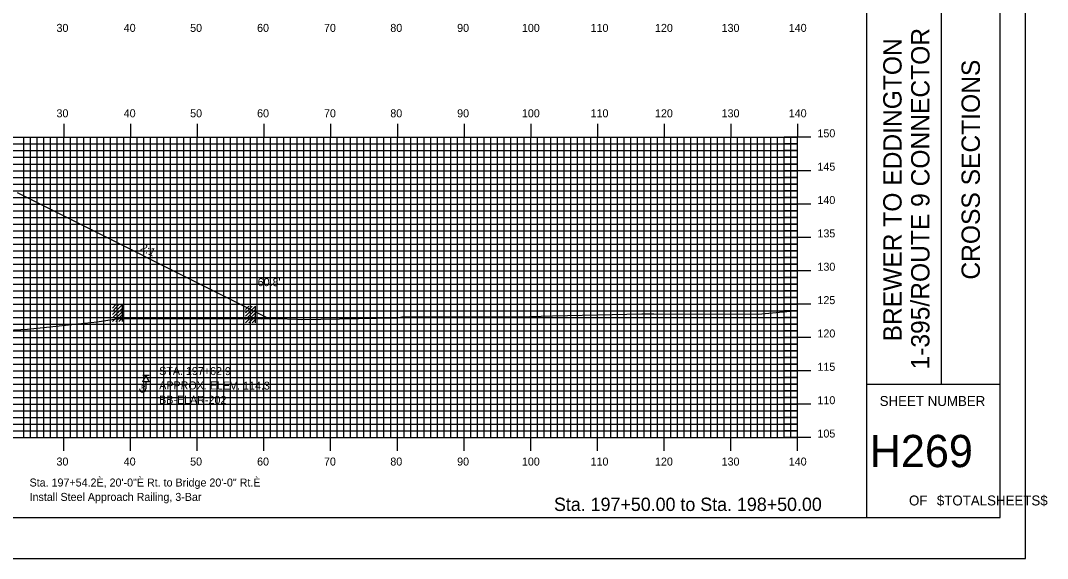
# Model space of a CAD drawing. Extents: x 1790124 to 1790467, y 442591 to 442811.
# Drawn here: x 1790313.2 to 1790467.2, y 442590.5 to 442671.2 of the extents above; entities that cross this region are included whole.
import ezdxf

# ---------------------------------------------------------------- set-up
doc = ezdxf.new("R2010")
doc.units = 0
for name, color, linetype in [('ANNOTATION', 7, 'Continuous'), ('BORDER', 7, 'Continuous'), ('BORING - REFUSAL', 7, 'Continuous'), ('D_Text_Standard', 7, 'Continuous'), ('H_V ANNOTATION', 7, 'Continuous'), ('M_Buildings_Rooftop', 7, 'Continuous'), ('M_Utilities_Pole', 7, 'Continuous'), ('MAJOR', 7, 'Continuous'), ('MINOR', 7, 'Continuous'), ('PLOT BOUNDARY', 7, 'Continuous'), ('S_Roadway_Centerline', 7, 'Continuous')]:
    doc.layers.add(name, color=color, linetype=linetype)

msp = doc.modelspace()

# ---------------------------------------------------------------- linework, layer by layer
at = {"layer": 'ANNOTATION'}
msp.add_line((1790312.7, 442645.4), (1790350.54, 442626.48), dxfattribs=at)
at = {"layer": 'BORDER'}
for p, q in [((1790440.1, 442596.67), (1790440.1, 442806.67)), ((1790451.28, 442616.67), (1790451.28, 442686.67)), ((1790440.1, 442616.67), (1790460.1, 442616.67))]:
    msp.add_line(p, q, dxfattribs=at)
msp.add_lwpolyline([(1790140.1, 442596.67), (1790460.1, 442596.67), (1790460.1, 442806.67), (1790140.1, 442806.67)], close=True, dxfattribs=at)
at = {"layer": 'BORING - REFUSAL'}
for p, q in [((1790332.48, 442617.97), (1790331.52, 442617.97)), ((1790332, 442617.01), (1790332, 442615.95))]:
    msp.add_line(p, q, dxfattribs=at)
msp.add_lwpolyline([(1790332, 442617.97), (1790332.48, 442617.01), (1790331.52, 442617.01)], close=True, dxfattribs=at)
msp.add_arc((1790331.51, 442615.95), 0.485, 180, 0, dxfattribs=at)
at = {"layer": 'M_Buildings_Rooftop'}
for p, q in [((1790326.98, 442627.09), (1790328.49, 442628.6)), ((1790326.98, 442627.58), (1790327.96, 442628.6)), ((1790326.98, 442628.08), (1790327.47, 442628.6)), ((1790326.98, 442626.6), (1790328.49, 442628.08)), ((1790328.49, 442626.07), (1790328.49, 442628.6)), ((1790346.95, 442626.87), (1790348.45, 442628.38)), ((1790346.95, 442627.36), (1790347.93, 442628.38)), ((1790346.95, 442627.85), (1790347.44, 442628.38)), ((1790346.95, 442626.38), (1790348.45, 442627.85)), ((1790348.45, 442625.85), (1790348.45, 442628.38)), ((1790326.98, 442626.07), (1790328.49, 442627.58)), ((1790327.47, 442626.07), (1790328.49, 442627.09)), ((1790327.96, 442626.07), (1790328.49, 442626.6)), ((1790346.95, 442625.85), (1790348.45, 442627.36)), ((1790347.44, 442625.85), (1790348.45, 442626.87)), ((1790347.93, 442625.85), (1790348.45, 442626.38))]:
    msp.add_line(p, q, dxfattribs=at)
at = {"layer": 'M_Utilities_Pole'}
msp.add_line((1790317.84, 442626.06), (1790317.84, 442626.04), dxfattribs=at)
msp.add_circle((1790317.84, 442626.05), 0.00417, dxfattribs=at)
at = {"layer": 'MAJOR'}
for p, q in [((1790319.7, 442655.67), (1790319.7, 442653.67)), ((1790329.7, 442655.67), (1790329.7, 442653.67)), ((1790339.7, 442655.67), (1790339.7, 442653.67)), ((1790349.7, 442655.67), (1790349.7, 442653.67)), ((1790359.7, 442655.67), (1790359.7, 442653.67)), ((1790369.7, 442655.67), (1790369.7, 442653.67)), ((1790379.7, 442655.67), (1790379.7, 442653.67)), ((1790389.7, 442655.67), (1790389.7, 442653.67)), ((1790399.7, 442655.67), (1790399.7, 442653.67)), ((1790409.7, 442655.67), (1790409.7, 442653.67)), ((1790419.7, 442655.67), (1790419.7, 442653.67)), ((1790429.7, 442655.67), (1790429.7, 442653.67)), ((1790149.7, 442653.67), (1790429.7, 442653.67)), ((1790149.7, 442653.67), (1790429.7, 442653.67)), ((1790319.7, 442608.67), (1790319.7, 442653.67)), ((1790329.7, 442608.67), (1790329.7, 442653.67)), ((1790339.7, 442608.67), (1790339.7, 442653.67)), ((1790349.7, 442608.67), (1790349.7, 442653.67)), ((1790359.7, 442608.67), (1790359.7, 442653.67)), ((1790369.7, 442608.67), (1790369.7, 442653.67)), ((1790379.7, 442608.67), (1790379.7, 442653.67)), ((1790389.7, 442608.67), (1790389.7, 442653.67)), ((1790399.7, 442608.67), (1790399.7, 442653.67)), ((1790409.7, 442608.67), (1790409.7, 442653.67)), ((1790419.7, 442608.67), (1790419.7, 442653.67)), ((1790431.7, 442653.67), (1790427.69, 442653.67)), ((1790429.7, 442608.67), (1790429.7, 442653.67)), ((1790429.7, 442608.67), (1790429.7, 442653.67)), ((1790149.7, 442648.67), (1790429.7, 442648.67)), ((1790431.7, 442648.67), (1790427.69, 442648.67)), ((1790149.7, 442643.67), (1790429.7, 442643.67)), ((1790431.7, 442643.67), (1790427.69, 442643.67)), ((1790149.7, 442638.67), (1790429.7, 442638.67)), ((1790431.7, 442638.67), (1790427.69, 442638.67)), ((1790149.7, 442633.67), (1790429.7, 442633.67)), ((1790431.7, 442633.67), (1790427.69, 442633.67)), ((1790149.7, 442628.67), (1790429.7, 442628.67)), ((1790431.7, 442628.67), (1790427.69, 442628.67)), ((1790149.7, 442623.67), (1790429.7, 442623.67)), ((1790431.7, 442623.67), (1790427.69, 442623.67)), ((1790149.7, 442618.67), (1790429.7, 442618.67)), ((1790431.7, 442618.67), (1790427.69, 442618.67)), ((1790149.7, 442613.67), (1790429.7, 442613.67)), ((1790431.7, 442613.67), (1790427.69, 442613.67)), ((1790149.7, 442608.67), (1790429.7, 442608.67)), ((1790149.7, 442608.67), (1790429.7, 442608.67)), ((1790319.7, 442606.66), (1790319.7, 442608.67)), ((1790329.7, 442606.66), (1790329.7, 442608.67)), ((1790339.7, 442606.66), (1790339.7, 442608.67)), ((1790349.7, 442606.66), (1790349.7, 442608.67)), ((1790359.7, 442606.66), (1790359.7, 442608.67)), ((1790369.7, 442606.66), (1790369.7, 442608.67)), ((1790379.7, 442606.66), (1790379.7, 442608.67)), ((1790389.7, 442606.66), (1790389.7, 442608.67)), ((1790399.7, 442606.66), (1790399.7, 442608.67)), ((1790409.7, 442606.66), (1790409.7, 442608.67)), ((1790419.7, 442606.66), (1790419.7, 442608.67)), ((1790431.7, 442608.67), (1790427.69, 442608.67)), ((1790429.7, 442606.66), (1790429.7, 442608.67))]:
    msp.add_line(p, q, dxfattribs=at)
at = {"layer": 'MINOR'}
for p, q in [((1790149.7, 442652.67), (1790429.7, 442652.67)), ((1790313.7, 442608.67), (1790313.7, 442653.67)), ((1790314.7, 442608.67), (1790314.7, 442653.67)), ((1790315.7, 442608.67), (1790315.7, 442653.67)), ((1790316.7, 442608.67), (1790316.7, 442653.67)), ((1790317.7, 442608.67), (1790317.7, 442653.67)), ((1790318.7, 442608.67), (1790318.7, 442653.67)), ((1790320.7, 442608.67), (1790320.7, 442653.67)), ((1790321.7, 442608.67), (1790321.7, 442653.67)), ((1790322.7, 442608.67), (1790322.7, 442653.67)), ((1790323.7, 442608.67), (1790323.7, 442653.67)), ((1790324.7, 442608.67), (1790324.7, 442653.67)), ((1790325.7, 442608.67), (1790325.7, 442653.67)), ((1790326.7, 442608.67), (1790326.7, 442653.67)), ((1790327.7, 442608.67), (1790327.7, 442653.67)), ((1790328.7, 442608.67), (1790328.7, 442653.67)), ((1790330.7, 442608.67), (1790330.7, 442653.67)), ((1790331.7, 442608.67), (1790331.7, 442653.67)), ((1790332.7, 442608.67), (1790332.7, 442653.67)), ((1790333.7, 442608.67), (1790333.7, 442653.67)), ((1790334.7, 442608.67), (1790334.7, 442653.67)), ((1790335.7, 442608.67), (1790335.7, 442653.67)), ((1790336.7, 442608.67), (1790336.7, 442653.67)), ((1790337.7, 442608.67), (1790337.7, 442653.67)), ((1790338.7, 442608.67), (1790338.7, 442653.67)), ((1790340.7, 442608.67), (1790340.7, 442653.67)), ((1790341.7, 442608.67), (1790341.7, 442653.67)), ((1790342.7, 442608.67), (1790342.7, 442653.67)), ((1790343.7, 442608.67), (1790343.7, 442653.67)), ((1790344.7, 442608.67), (1790344.7, 442653.67)), ((1790345.7, 442608.67), (1790345.7, 442653.67)), ((1790346.7, 442608.67), (1790346.7, 442653.67)), ((1790347.7, 442608.67), (1790347.7, 442653.67)), ((1790348.7, 442608.67), (1790348.7, 442653.67)), ((1790350.7, 442608.67), (1790350.7, 442653.67)), ((1790351.7, 442608.67), (1790351.7, 442653.67)), ((1790352.7, 442608.67), (1790352.7, 442653.67)), ((1790353.7, 442608.67), (1790353.7, 442653.67)), ((1790354.7, 442608.67), (1790354.7, 442653.67)), ((1790355.7, 442608.67), (1790355.7, 442653.67)), ((1790356.7, 442608.67), (1790356.7, 442653.67)), ((1790357.7, 442608.67), (1790357.7, 442653.67)), ((1790358.7, 442608.67), (1790358.7, 442653.67)), ((1790360.7, 442608.67), (1790360.7, 442653.67)), ((1790361.7, 442608.67), (1790361.7, 442653.67)), ((1790362.7, 442608.67), (1790362.7, 442653.67)), ((1790363.7, 442608.67), (1790363.7, 442653.67)), ((1790364.7, 442608.67), (1790364.7, 442653.67)), ((1790365.7, 442608.67), (1790365.7, 442653.67)), ((1790366.7, 442608.67), (1790366.7, 442653.67)), ((1790367.7, 442608.67), (1790367.7, 442653.67)), ((1790368.7, 442608.67), (1790368.7, 442653.67)), ((1790370.7, 442608.67), (1790370.7, 442653.67)), ((1790371.7, 442608.67), (1790371.7, 442653.67)), ((1790372.7, 442608.67), (1790372.7, 442653.67)), ((1790373.7, 442608.67), (1790373.7, 442653.67)), ((1790374.7, 442608.67), (1790374.7, 442653.67)), ((1790375.7, 442608.67), (1790375.7, 442653.67)), ((1790376.7, 442608.67), (1790376.7, 442653.67)), ((1790377.7, 442608.67), (1790377.7, 442653.67)), ((1790378.7, 442608.67), (1790378.7, 442653.67)), ((1790380.7, 442608.67), (1790380.7, 442653.67)), ((1790381.7, 442608.67), (1790381.7, 442653.67)), ((1790382.7, 442608.67), (1790382.7, 442653.67)), ((1790383.7, 442608.67), (1790383.7, 442653.67)), ((1790384.7, 442608.67), (1790384.7, 442653.67)), ((1790385.7, 442608.67), (1790385.7, 442653.67)), ((1790386.7, 442608.67), (1790386.7, 442653.67)), ((1790387.7, 442608.67), (1790387.7, 442653.67)), ((1790388.7, 442608.67), (1790388.7, 442653.67)), ((1790390.7, 442608.67), (1790390.7, 442653.67)), ((1790391.7, 442608.67), (1790391.7, 442653.67)), ((1790392.7, 442608.67), (1790392.7, 442653.67)), ((1790393.7, 442608.67), (1790393.7, 442653.67)), ((1790394.7, 442608.67), (1790394.7, 442653.67)), ((1790395.7, 442608.67), (1790395.7, 442653.67)), ((1790396.7, 442608.67), (1790396.7, 442653.67)), ((1790397.7, 442608.67), (1790397.7, 442653.67)), ((1790398.7, 442608.67), (1790398.7, 442653.67)), ((1790400.7, 442608.67), (1790400.7, 442653.67)), ((1790401.7, 442608.67), (1790401.7, 442653.67)), ((1790402.7, 442608.67), (1790402.7, 442653.67)), ((1790403.7, 442608.67), (1790403.7, 442653.67)), ((1790404.7, 442608.67), (1790404.7, 442653.67)), ((1790405.7, 442608.67), (1790405.7, 442653.67)), ((1790406.7, 442608.67), (1790406.7, 442653.67)), ((1790407.7, 442608.67), (1790407.7, 442653.67)), ((1790408.7, 442608.67), (1790408.7, 442653.67)), ((1790410.7, 442608.67), (1790410.7, 442653.67)), ((1790411.7, 442608.67), (1790411.7, 442653.67)), ((1790412.7, 442608.67), (1790412.7, 442653.67)), ((1790413.7, 442608.67), (1790413.7, 442653.67)), ((1790414.7, 442608.67), (1790414.7, 442653.67)), ((1790415.7, 442608.67), (1790415.7, 442653.67)), ((1790416.7, 442608.67), (1790416.7, 442653.67)), ((1790417.7, 442608.67), (1790417.7, 442653.67)), ((1790418.7, 442608.67), (1790418.7, 442653.67)), ((1790420.7, 442608.67), (1790420.7, 442653.67)), ((1790421.7, 442608.67), (1790421.7, 442653.67)), ((1790422.7, 442608.67), (1790422.7, 442653.67)), ((1790423.7, 442608.67), (1790423.7, 442653.67)), ((1790424.7, 442608.67), (1790424.7, 442653.67)), ((1790425.7, 442608.67), (1790425.7, 442653.67)), ((1790426.7, 442608.67), (1790426.7, 442653.67)), ((1790429.7, 442652.67), (1790427.69, 442652.67)), ((1790427.7, 442608.67), (1790427.7, 442653.67)), ((1790428.7, 442608.67), (1790428.7, 442653.67)), ((1790149.7, 442651.67), (1790429.7, 442651.67)), ((1790429.7, 442651.67), (1790427.69, 442651.67)), ((1790149.7, 442650.67), (1790429.7, 442650.67)), ((1790149.7, 442649.67), (1790429.7, 442649.67)), ((1790429.7, 442650.67), (1790427.69, 442650.67)), ((1790429.7, 442649.67), (1790427.69, 442649.67)), ((1790149.7, 442647.67), (1790429.7, 442647.67)), ((1790149.7, 442646.67), (1790429.7, 442646.67)), ((1790429.7, 442647.67), (1790427.69, 442647.67)), ((1790429.7, 442646.67), (1790427.69, 442646.67)), ((1790149.7, 442645.67), (1790429.7, 442645.67)), ((1790429.7, 442645.67), (1790427.69, 442645.67)), ((1790149.7, 442644.67), (1790429.7, 442644.67)), ((1790429.7, 442644.67), (1790427.69, 442644.67)), ((1790149.7, 442642.67), (1790429.7, 442642.67)), ((1790429.7, 442642.67), (1790427.69, 442642.67)), ((1790149.7, 442641.67), (1790429.7, 442641.67)), ((1790149.7, 442640.67), (1790429.7, 442640.67)), ((1790429.7, 442641.67), (1790427.69, 442641.67)), ((1790429.7, 442640.67), (1790427.69, 442640.67)), ((1790149.7, 442639.67), (1790429.7, 442639.67)), ((1790429.7, 442639.67), (1790427.69, 442639.67)), ((1790149.7, 442637.67), (1790429.7, 442637.67)), ((1790429.7, 442637.67), (1790427.69, 442637.67)), ((1790149.7, 442636.67), (1790429.7, 442636.67)), ((1790149.7, 442635.67), (1790429.7, 442635.67)), ((1790429.7, 442636.67), (1790427.69, 442636.67)), ((1790429.7, 442635.67), (1790427.69, 442635.67)), ((1790149.7, 442634.67), (1790429.7, 442634.67)), ((1790429.7, 442634.67), (1790427.69, 442634.67)), ((1790149.7, 442632.67), (1790429.7, 442632.67)), ((1790429.7, 442632.67), (1790427.69, 442632.67)), ((1790149.7, 442631.67), (1790429.7, 442631.67)), ((1790429.7, 442631.67), (1790427.69, 442631.67)), ((1790149.7, 442630.67), (1790429.7, 442630.67)), ((1790149.7, 442629.67), (1790429.7, 442629.67)), ((1790429.7, 442630.67), (1790427.69, 442630.67)), ((1790429.7, 442629.67), (1790427.69, 442629.67)), ((1790149.7, 442627.67), (1790429.7, 442627.67)), ((1790149.7, 442626.67), (1790429.7, 442626.67)), ((1790429.7, 442627.67), (1790427.69, 442627.67)), ((1790429.7, 442626.67), (1790427.69, 442626.67)), ((1790149.7, 442625.67), (1790429.7, 442625.67)), ((1790429.7, 442625.67), (1790427.69, 442625.67)), ((1790149.7, 442624.67), (1790429.7, 442624.67)), ((1790429.7, 442624.67), (1790427.69, 442624.67)), ((1790149.7, 442622.67), (1790429.7, 442622.67)), ((1790429.7, 442622.67), (1790427.69, 442622.67)), ((1790149.7, 442621.67), (1790429.7, 442621.67)), ((1790149.7, 442620.67), (1790429.7, 442620.67)), ((1790429.7, 442621.67), (1790427.69, 442621.67)), ((1790429.7, 442620.67), (1790427.69, 442620.67)), ((1790149.7, 442619.67), (1790429.7, 442619.67)), ((1790429.7, 442619.67), (1790427.69, 442619.67)), ((1790149.7, 442617.67), (1790429.7, 442617.67)), ((1790429.7, 442617.67), (1790427.69, 442617.67)), ((1790149.7, 442616.67), (1790429.7, 442616.67)), ((1790149.7, 442615.67), (1790429.7, 442615.67)), ((1790429.7, 442616.67), (1790427.69, 442616.67)), ((1790429.7, 442615.67), (1790427.69, 442615.67)), ((1790149.7, 442614.67), (1790429.7, 442614.67)), ((1790429.7, 442614.67), (1790427.69, 442614.67)), ((1790149.7, 442612.67), (1790429.7, 442612.67)), ((1790429.7, 442612.67), (1790427.69, 442612.67)), ((1790149.7, 442611.67), (1790429.7, 442611.67)), ((1790429.7, 442611.67), (1790427.69, 442611.67)), ((1790149.7, 442610.67), (1790429.7, 442610.67)), ((1790149.7, 442609.67), (1790429.7, 442609.67)), ((1790429.7, 442610.67), (1790427.69, 442610.67)), ((1790429.7, 442609.67), (1790427.69, 442609.67))]:
    msp.add_line(p, q, dxfattribs=at)
at = {"layer": 'PLOT BOUNDARY'}
msp.add_lwpolyline([(1790123.91, 442590.55), (1790463.91, 442590.55), (1790463.91, 442810.55), (1790123.91, 442810.55)], close=True, dxfattribs=at)
at = {"layer": 'S_Roadway_Centerline'}
msp.add_lwpolyline([(1790308.09, 442624.59), (1790314.26, 442624.9), (1790324.7, 442626.01), (1790326.28, 442626.25), (1790327.6, 442626.48), (1790331.09, 442626.51), (1790349.29, 442626.47), (1790351.76, 442626.49), (1790354.62, 442626.4), (1790355.39, 442626.35), (1790369.53, 442626.59), (1790369.73, 442626.6), (1790369.75, 442626.61), (1790370.39, 442626.74), (1790372.69, 442626.74), (1790376.59, 442626.75), (1790389.57, 442626.81), (1790392.97, 442626.93), (1790406.37, 442627.21), (1790406.95, 442627.23), (1790408.15, 442627.21), (1790423.83, 442627.18), (1790429.7, 442627.71)], dxfattribs=at)

# ---------------------------------------------------------------- texts
at = {"layer": 'ANNOTATION'}
msp.add_text('2:1', height=1.2, rotation=333.4349, dxfattribs=at).set_placement((1790331.05, 442636.76))
for s, p in [('Sta. 197+54.2È, 20\'-0"È Rt. to Bridge 20\'-0" Rt.È', (1790314.55, 442601.33)), ('Install Steel Approach Railing, 3-Bar', (1790314.55, 442599.17))]:
    msp.add_text(s, height=1.2, dxfattribs=at).set_placement(p)
at = {"layer": 'BORDER'}
for s, p in [('1-395/ROUTE 9 CONNECTOR', (1790449.5, 442618.87)), ('BREWER TO EDDINGTON', (1790445.32, 442623.07)), ('CROSS SECTIONS', (1790457.06, 442632.34))]:
    msp.add_text(s, height=2.7557, rotation=90, dxfattribs=at).set_placement(p)
for s, height, p in [('SHEET NUMBER', 1.4905, (1790442.03, 442613.4)), ('H269', 4.839, (1790440.54, 442604.23)), ('OF', 1.491, (1790446.43, 442598.49)), ('$TOTALSHEETS$', 1.4905, (1790450.61, 442598.49))]:
    msp.add_text(s, height=height, dxfattribs=at).set_placement(p)
at = {"layer": 'BORING - REFUSAL'}
for s, p in [('STA. 197+62.9', (1790333.99, 442618.06)), ('APPROX. ELEV. 114.3', (1790333.99, 442615.9)), ('BB-ELAR-202', (1790333.98, 442613.74))]:
    msp.add_text(s, height=1.2, rotation=359.8142, dxfattribs=at).set_placement(p)
msp.add_text('R', height=0.64, dxfattribs=at).set_placement((1790331.29, 442615.89))
at = {"layer": 'D_Text_Standard'}
msp.add_text("60.8'", height=1.2, dxfattribs=at).set_placement((1790348.76, 442631.36))
at = {"layer": 'H_V ANNOTATION'}
for s, height, p in [('30', 1.2, (1790318.59, 442669.47)), ('40', 1.2, (1790328.67, 442669.47)), ('50', 1.2, (1790338.63, 442669.47)), ('60', 1.2, (1790348.67, 442669.47)), ('70', 1.2, (1790358.7, 442669.47)), ('80', 1.2, (1790368.65, 442669.47)), ('90', 1.2, (1790378.67, 442669.47)), ('100', 1.2, (1790388.38, 442669.47)), ('110', 1.2, (1790398.68, 442669.47)), ('120', 1.2, (1790408.34, 442669.47)), ('130', 1.2, (1790418.33, 442669.47)), ('140', 1.2, (1790428.4, 442669.47)), ('30', 1.2, (1790318.59, 442656.67)), ('40', 1.2, (1790328.67, 442656.67)), ('50', 1.2, (1790338.63, 442656.67)), ('60', 1.2, (1790348.67, 442656.67)), ('70', 1.2, (1790358.7, 442656.67)), ('80', 1.2, (1790368.65, 442656.67)), ('90', 1.2, (1790378.67, 442656.67)), ('100', 1.2, (1790388.38, 442656.67)), ('110', 1.2, (1790398.68, 442656.67)), ('120', 1.2, (1790408.34, 442656.67)), ('130', 1.2, (1790418.33, 442656.67)), ('140', 1.2, (1790428.4, 442656.67)), ('150', 1.2, (1790432.7, 442653.67)), ('145', 1.2, (1790432.7, 442648.67)), ('140', 1.2, (1790432.7, 442643.67)), ('135', 1.2, (1790432.7, 442638.67)), ('130', 1.2, (1790432.7, 442633.67)), ('125', 1.2, (1790432.7, 442628.67)), ('120', 1.2, (1790432.7, 442623.67)), ('115', 1.2, (1790432.7, 442618.67)), ('110', 1.2, (1790432.7, 442613.67)), ('105', 1.2, (1790432.7, 442608.67)), ('30', 1.2, (1790318.59, 442604.47)), ('40', 1.2, (1790328.67, 442604.47)), ('50', 1.2, (1790338.63, 442604.47)), ('60', 1.2, (1790348.67, 442604.47)), ('70', 1.2, (1790358.7, 442604.47)), ('80', 1.2, (1790368.65, 442604.47)), ('90', 1.2, (1790378.67, 442604.47)), ('100', 1.2, (1790388.38, 442604.47)), ('110', 1.2, (1790398.68, 442604.47)), ('120', 1.2, (1790408.34, 442604.47)), ('130', 1.2, (1790418.33, 442604.47)), ('140', 1.2, (1790428.4, 442604.47)), ('Sta. 197+50.00 to Sta. 198+50.00', 2.0004, (1790393.19, 442597.66))]:
    msp.add_text(s, height=height, dxfattribs=at).set_placement(p)

doc.saveas('drawing.dxf')
